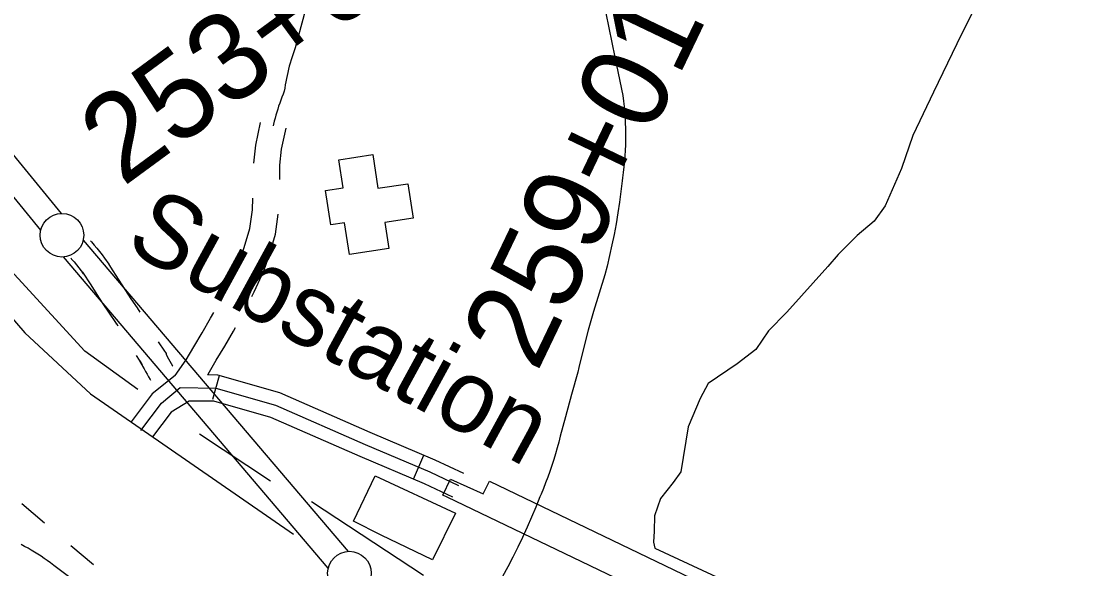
# Model space of a CAD drawing. Extents: x 3180038 to 3217926, y 922069 to 947485.
# Drawn here: x 3190489 to 3191717, y 941520 to 942147 of the extents above; entities that cross this region are included whole.
import ezdxf

# ---------------------------------------------------------------- set-up
doc = ezdxf.new("R2010")
doc.units = 0
for name, color, linetype in [('V-BLDG-OTLN', 7, 'Continuous'), ('V-LEVE-TOET', 7, 'Continuous'), ('V-RIVR-EDGE', 7, 'Continuous'), ('V-ROAD-CNTR', 7, 'Continuous'), ('V-RTRN-LOCK-CHMB', 7, 'Continuous'), ('V-SITE-STRC', 7, 'Continuous'), ('V-SURV-IDEN', 7, 'Continuous'), ('V-SURV-LINE', 7, 'Continuous'), ('V-TOPO-SHOR', 7, 'Continuous'), ('V-UTIL-LINE', 7, 'Continuous')]:
    doc.layers.add(name, color=color, linetype=linetype)

msp = doc.modelspace()

# ---------------------------------------------------------------- linework, layer by layer
at = {"layer": 'V-BLDG-OTLN'}
msp.add_lwpolyline([(3190892.2, 941994.5), (3190898.2, 941955.7), (3190932.4, 941961), (3190938.5, 941921.4), (3190906, 941916.4), (3190910.5, 941886.8), (3190865.6, 941879.9), (3190860, 941916.3), (3190844, 941913.8), (3190837.9, 941953.2), (3190858.3, 941956.4), (3190853.3, 941988.5)], close=True, dxfattribs=at)
at = {"layer": 'V-LEVE-TOET'}
for points in [[(3191142.4, 942241.2), (3191169.9, 942106.1), (3191179.1, 942062.1), (3191179.1, 942062.1), (3191179.8, 942055.8), (3191180.5, 942049.5), (3191181, 942043.2), (3191181.4, 942037), (3191181.7, 942030.7), (3191181.9, 942024.4), (3191181.9, 942018.1), (3191181.9, 942011.8), (3191181.8, 942005.4), (3191181.5, 941999.2), (3191181.1, 941992.9), (3191180.7, 941986.6), (3191180.1, 941980.3), (3191179.4, 941974), (3191178.6, 941967.8), (3191178.1, 941964.4), (3191178.1, 941964.4), (3191176.7, 941952), (3191175.1, 941939.7), (3191173.2, 941927.4), (3191171.1, 941915.1), (3191168.9, 941902.9), (3191166.4, 941890.7), (3191163.7, 941878.6), (3191160.8, 941866.5), (3191158.2, 941856.6), (3191158.2, 941856.6), (3191151.6, 941835.5), (3191145.2, 941814.4), (3191139.3, 941793.1), (3191133.7, 941771.8), (3191128.4, 941750.3), (3191127.2, 941745), (3191127.2, 941745), (3191120.1, 941719.3), (3191113.1, 941693.5), (3191107.1, 941671.5), (3191107.1, 941671.5), (3191105.5, 941664.7), (3191103.7, 941657.9), (3191101.7, 941651.2), (3191099.7, 941644.5), (3191097.5, 941637.8), (3191095.3, 941631.1), (3191092.9, 941624.5), (3191090.4, 941618), (3191087.8, 941611.5), (3191085.1, 941605), (3191083.7, 941601.9), (3191083.7, 941601.9), (3191079.1, 941590.1), (3191074.2, 941578.5), (3191069.1, 941566.9), (3191063.9, 941555.4), (3191058.4, 941544), (3191052.8, 941532.7), (3191047, 941521.5), (3191041, 941510.4)], [(3190625.2, 941458.1), (3190613.8, 941464.5), (3190602.4, 941471.1), (3190591.2, 941478), (3190580.2, 941485), (3190569.2, 941492.2), (3190558.4, 941499.7), (3190547.7, 941507.3), (3190537.1, 941515), (3190526.7, 941523), (3190522.6, 941526.2), (3190522.6, 941526.2), (3190519.1, 941528.7), (3190515.5, 941531.3), (3190511.9, 941533.7), (3190508.2, 941536.1), (3190504.5, 941538.4), (3190500.7, 941540.7), (3190497, 941542.9), (3190493.1, 941545), (3190489.3, 941547.1)]]:
    msp.add_lwpolyline(points, dxfattribs=at)
at = {"layer": 'V-RIVR-EDGE'}
msp.add_lwpolyline([(3191604.3, 942206), (3191567.3, 942132.4), (3191535, 942066.1), (3191511.5, 942016.4), (3191498.4, 941978.6), (3191479.7, 941935.6), (3191467.2, 941918), (3191447.4, 941901.4), (3191425.6, 941879.7), (3191414.1, 941866.2), (3191366.8, 941813.5), (3191346, 941792.2), (3191331.4, 941771), (3191310.1, 941754.5), (3191276.9, 941731.7), (3191267.5, 941714.6), (3191253.9, 941682), (3191245.5, 941630.7), (3191236.7, 941618.3), (3191222.1, 941600.1), (3191215.3, 941579.9), (3191214.8, 941562.3), (3191214.2, 941549.9), (3191215.7, 941543.1), (3191361.8, 941474.8)], dxfattribs=at)
at = {"layer": 'V-ROAD-CNTR'}
for p, q in [((3190708.7, 941713.7), (3190716.6, 941741)), ((3190939.1, 941622), (3190950.8, 941649.6))]:
    msp.add_line(p, q, dxfattribs=at)
for points in [[(3190822.5, 942188), (3190803.4, 942116.8), (3190803.4, 942116.8), (3190802.1, 942113.4), (3190800.8, 942109.9), (3190799.7, 942106.4), (3190798.5, 942102.9), (3190797.5, 942099.4), (3190796.5, 942095.8), (3190795.6, 942092.3), (3190794.7, 942088.7), (3190793.9, 942085.1), (3190793.2, 942081.5), (3190792.5, 942077.9), (3190791.9, 942074.3), (3190791.3, 942070.7), (3190790.8, 942067), (3190790.8, 942067), (3190790.8, 942067), (3190789.4, 942063.6), (3190788, 942060.3), (3190786.7, 942056.9), (3190785.5, 942053.5), (3190784.3, 942050.1), (3190783.2, 942046.6), (3190782.1, 942043.1), (3190781.1, 942039.7), (3190780.2, 942036.2), (3190779.3, 942032.6), (3190778.5, 942029.1), (3190778.1, 942027.4)], [(3190755.8, 941984.4), (3190758, 942005.2), (3190763.5, 942031.1)], [(3190785.5, 941966), (3190785.7, 941982.1), (3190787.7, 942000.5), (3190792.9, 942024.8)], [(3190728.5, 941848.9), (3190729.1, 941850), (3190739.4, 941872.3), (3190744.9, 941887.9), (3190751.3, 941909.5), (3190754.3, 941930.9), (3190754.8, 941944.4)], [(3190753.4, 941831.5), (3190756.1, 941837), (3190767.3, 941861), (3190773.5, 941878.7), (3190780.7, 941903.1), (3190783.9, 941926)], [(3190568.5, 941895.6), (3190569.7, 941894.2), (3190572.8, 941890.6), (3190575.9, 941886.9), (3190578.9, 941883.1), (3190581.8, 941879.4), (3190584.7, 941875.5), (3190589.6, 941868.7), (3190589.6, 941868.2), (3190594.1, 941861.1), (3190601.1, 941850.4), (3190608, 941839.8), (3190615, 941829.1), (3190622.1, 941818.5), (3190625.3, 941813.7)], [(3190411.4, 941884.3), (3190493.3, 941790), (3190568.7, 941720), (3190801.4, 941559)], [(3190545.9, 941875.8), (3190547, 941874.6), (3190549.8, 941871.3), (3190552.6, 941868), (3190555.3, 941864.6), (3190557.9, 941861.2), (3190560.5, 941857.7), (3190559.6, 941859), (3190559.6, 941859.5), (3190568.9, 941844.9), (3190575.9, 941834.1), (3190582.9, 941823.3), (3190590, 941812.6), (3190597.1, 941801.9), (3190598.4, 941800), (3190598.4, 941800.5), (3190599.9, 941797.8)], [(3190665.7, 941741.2), (3190678.3, 941759), (3190687.1, 941773.9), (3190696.8, 941789.8), (3190706.3, 941806.6), (3190710, 941813.4)], [(3190702.8, 941741.7), (3190703.5, 941742.7), (3190712.8, 941758.5), (3190722.7, 941774.6), (3190732.5, 941792), (3190734.7, 941796.1)], [(3190646.2, 941779.8), (3190647.1, 941778.4), (3190652.7, 941770.2), (3190655.4, 941766.2), (3190655.2, 941765.4), (3190656.6, 941762.7), (3190658, 941760), (3190659.5, 941757.4), (3190661, 941754.8), (3190662.6, 941752.2), (3190662.9, 941751.7)], [(3190620.9, 941763.8), (3190627.8, 941753.4), (3190625.4, 941756.9), (3190625.4, 941758), (3190628.4, 941751.9), (3190630.1, 941748.7), (3190631.7, 941745.6), (3190633.4, 941742.6), (3190635.2, 941739.5), (3190637, 941736.5), (3190637.5, 941735.8)], [(3190665.7, 941741.2), (3190639.2, 941719.8), (3190615.1, 941687.9)], [(3190996.8, 941628.6), (3190963.9, 941644.1), (3190889.4, 941675.6), (3190785.7, 941721.1), (3190714.6, 941741.5), (3190702.8, 941741.7)], [(3190626.4, 941678), (3190650.1, 941709.4), (3190671.4, 941727.1), (3190712.4, 941726.6), (3190780.6, 941706.9), (3190883.5, 941661.9), (3190957.8, 941630.4), (3190990.4, 941615)], [(3190681.7, 941711.7), (3190661, 941698.9), (3190639.8, 941670.8)], [(3190984, 941601.4), (3190951.7, 941616.7), (3190877.6, 941648.1), (3190775.5, 941692.8), (3190710.2, 941711.6), (3190681.7, 941711.7)]]:
    msp.add_lwpolyline(points, dxfattribs=at)
at = {"layer": 'V-RTRN-LOCK-CHMB'}
msp.add_lwpolyline([(3190972.6, 941603.9), (3190981.3, 941622.2), (3191018.6, 941605.3), (3191026, 941619.8), (3191257.3, 941508.7), (3191920.1, 941187.8), (3191902.7, 941154), (3191660.3, 941270.3), (3191623.6, 941196.4), (3191215, 941393.3), (3191241.2, 941451.2), (3191228.2, 941481), (3190977.4, 941601.4)], close=True, dxfattribs=at)
at = {"layer": 'V-SITE-STRC'}
msp.add_lwpolyline([(3190870, 941574), (3190894.9, 941625.8), (3190987.1, 941583.3), (3190960.7, 941529.6), (3190901.9, 941557.8)], close=True, dxfattribs=at)
at = {"layer": 'V-SURV-LINE'}
for points in [[(3190410.6, 942078.3), (3190534.9, 941926.8)], [(3190511.7, 941907.8), (3190387.4, 942059.3)], [(3190560.3, 941896.4), (3190864, 941539.3)], [(3190841.2, 941519.9), (3190537.5, 941877)]]:
    msp.add_lwpolyline(points, dxfattribs=at)
for centre in [(3190535.9, 941901.9), (3190865.5, 941514.4)]:
    msp.add_circle(centre, 25, dxfattribs=at)
at = {"layer": 'V-TOPO-SHOR'}
for p, q in [((3190693.7, 941674.2), (3190774.8, 941620.2)), ((3190822.1, 941596.6), (3190950.5, 941512.1))]:
    msp.add_line(p, q, dxfattribs=at)
msp.add_lwpolyline([(3190622.8, 941724.9), (3190562, 941768.8), (3190447.1, 941893.8), (3190376.2, 941988.4), (3190325.5, 942056), (3190298.5, 942120.1), (3190274, 942186.4), (3190245.3, 942289.5), (3190226.7, 942409.4), (3190220, 942524.2), (3190226.7, 942576.6), (3190230.1, 942635.7), (3190250.4, 942743.8), (3190329.8, 943017.4)], dxfattribs=at)
at = {"layer": 'V-UTIL-LINE'}
for points in [[(3190489.8, 941594.3), (3190515.7, 941572.2)], [(3190546.1, 941546.2), (3190572, 941524.2)]]:
    msp.add_lwpolyline(points, dxfattribs=at)

# ---------------------------------------------------------------- texts
at = {"layer": 'V-SITE-STRC'}
msp.add_text('Substation', height=83, rotation=331.3821, dxfattribs=at).set_placement((3190605.9, 941887.1))
at = {"layer": 'V-SURV-IDEN'}
for s, rotation, p in [('253+92.7', 36.3105, (3190605.7, 941956.7)), ('259+01.4', 64.4211, (3191080.4, 941743.3))]:
    msp.add_text(s, height=100, rotation=rotation, dxfattribs=at).set_placement(p)

doc.saveas('drawing.dxf')
